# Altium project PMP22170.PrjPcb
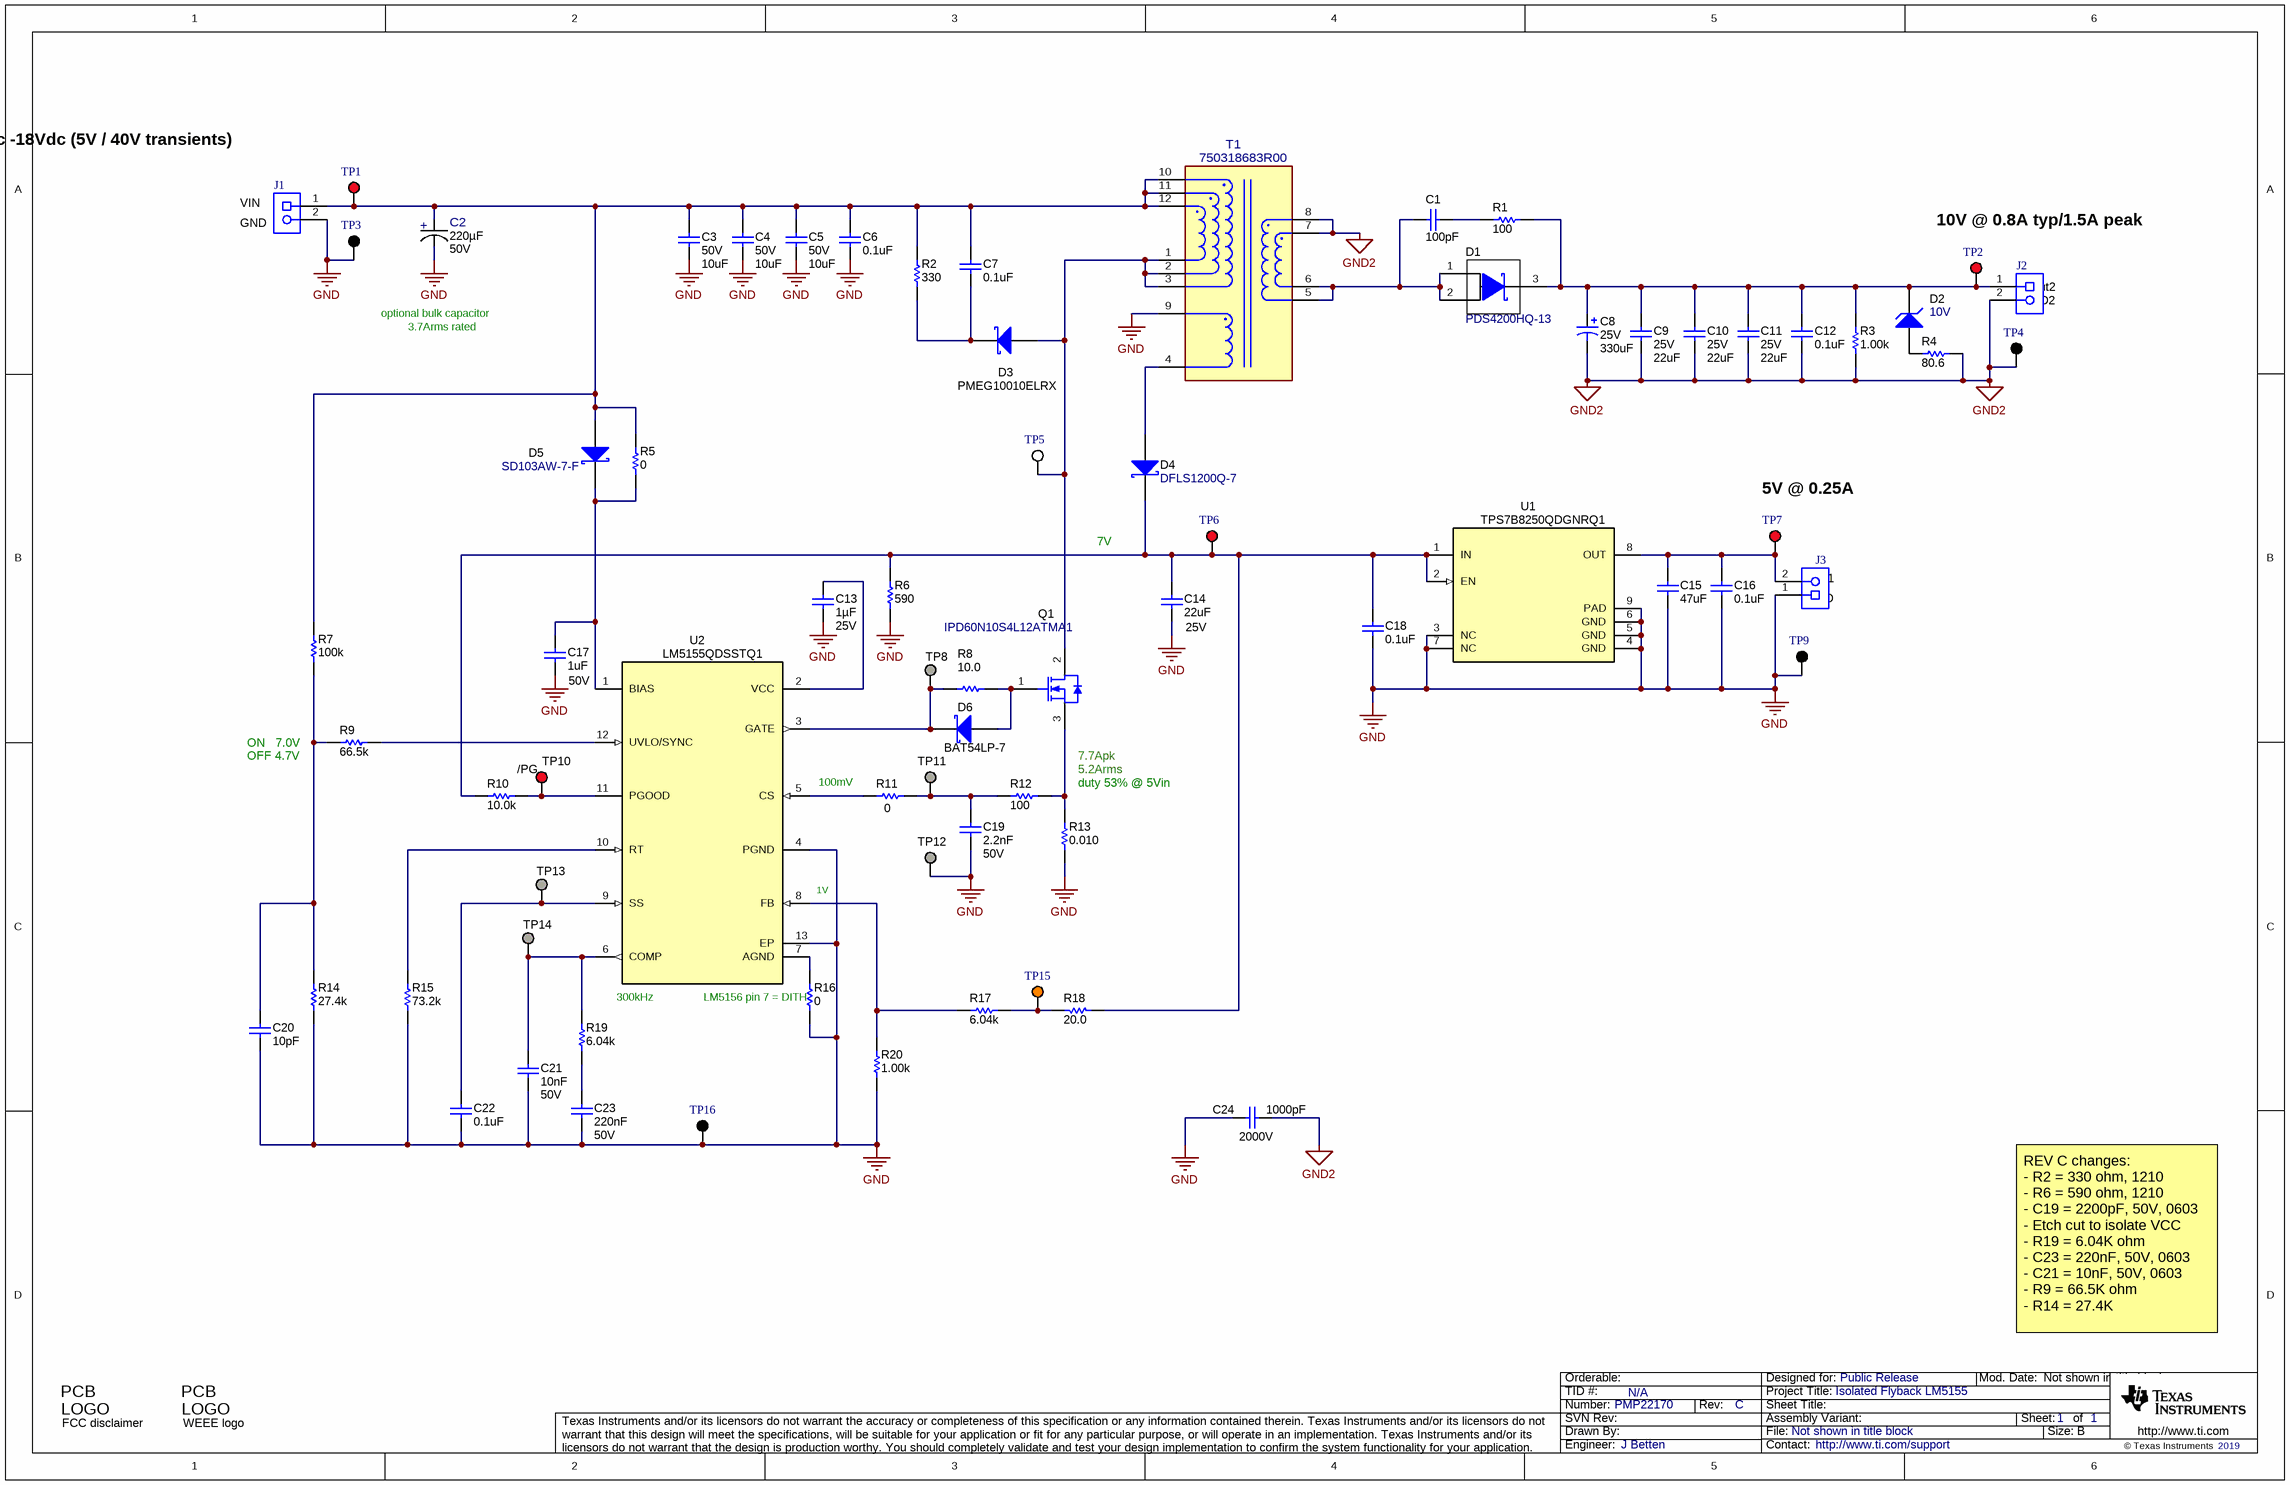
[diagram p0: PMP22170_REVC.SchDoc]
TID: N/A; TechSupport: http://www.ti.com/support; SCH_Rev: C; PRJ_Title: Isolated Flyback LM5155; PRJ_Number: PMP22170; PRJ_Engineer: J Betten; PRJ_Customer: Public Release; PCB_Rev: A; PCB_Layout: J Betten; CopyrightYear: 2019
1 sheet, 75 parts. Net scope: global (net labels, ports and power ports of the same name join across sheets).
Board file: PMP22170_REVA.PcbDoc

## Sheet PMP22170_REVC.SchDoc
size 431 x 279 mm; Date: Not shown in title block; ApprovedBy: Not shown in title block; CheckedBy: Not shown in title block; Author: Not shown in title block; CompanyName: Not shown in title block; Engineer: Not shown in title block; Organization: Not shown in title block; Address1: Not shown in title block; Address2: Not shown in title block; Address3: Not shown in title block; Address4: Not shown in title block; DocumentNumber: 1; Revision: Use project parameter SCH_Rev; SheetNumber: 1; SheetTotal: 1; PageSetup: Record=PageOptions¦CenterHorizontal=True¦CenterVertical=True¦PrintScale=1.00¦XCorrection=1.00¦YCorrection=1.00¦PrintKind=0¦BorderSize=5000000¦LeftOffset=0¦BottomOffset=0¦Orientation=2¦PaperLength=1000¦PaperWidth=1000¦Scale=100¦PaperSource=15¦PrintQuality=600¦MediaType=1¦DitherType=10¦PaperKind=Letter¦PrintScaleMode=1

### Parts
C1  ValueDisplayed: 100pF  [0805_HV]  (hidden comment: Capacitor)
C2  Cap_F: 220µF  VDC_V: 50V  [FP-EEHZS1H221P_RADIAL_SMD-MFG]  (hidden comment: EEH-ZS1H221V)
C3  VDC_V: 50V  ValueDisplayed: 10uF  [1210_280]  (hidden comment: UMK325AB7106KMHT)
C4  VDC_V: 50V  ValueDisplayed: 10uF  [1210_280]  (hidden comment: UMK325AB7106KMHT)
C5  VDC_V: 50V  ValueDisplayed: 10uF  [1210_280]  (hidden comment: UMK325AB7106KMHT)
C6  ValueDisplayed: 0.1uF  [0603]  (hidden comment: Capacitor)
C7  ValueDisplayed: 0.1uF  [0603]  (hidden comment: Capacitor)
C8  VDC_V: 25V  ValueDisplayed: 330uF  [SM_RADIAL_10BMM]  (hidden comment: EEHZC1E331P)
C9  VDC_V: 25V  ValueDisplayed: 22uF  [1210_270]  (hidden comment: TMK325B7226KMHT)
C10  VDC_V: 25V  ValueDisplayed: 22uF  [1210_270]  (hidden comment: TMK325B7226KMHT)
C11  VDC_V: 25V  ValueDisplayed: 22uF  [1210_270]  (hidden comment: TMK325B7226KMHT)
C12  ValueDisplayed: 0.1uF  [0603]  (hidden comment: Capacitor)
C13  Cap_F: 1µF  VDC_V: 25V  [0603]  (hidden comment: GCM188R71E105KA64D)
C14  ValueDisplayed: 22uF  Value2: 25V  [1210_270]  (hidden comment: Capacitor)
C15  ValueDisplayed: 47uF  [1210_270]  (hidden comment: Capacitor)
C16  ValueDisplayed: 0.1uF  [0603]  (hidden comment: Capacitor)
C17  ValueDisplayed: 1uF  Value2: 50V  [0805]  (hidden comment: Capacitor)
C18  ValueDisplayed: 0.1uF  [0603]  (hidden comment: Capacitor)
C19  Cap_F: 2.2nF  VDC_V: 50V  [0603]  (hidden comment: GRM188R71H222KA01D)
C20  ValueDisplayed: 10pF  [0603]  (hidden comment: Capacitor)
C21  Cap_F: 10nF  VDC_V: 50V  [0603]  (hidden comment: GCM188R71H103KA37D)
C22  ValueDisplayed: 0.1uF  [0603]  (hidden comment: Capacitor)
C23  Cap_F: 220nF  VDC_V: 50V  [0603]  (hidden comment: GCM188R71H224KA64D)
C24  ValueDisplayed: 1000pF  Value2: 2000V  [1808]  (hidden comment: Capacitor)
D1  PDS4200HQ-13  [POWERDI5]
D2  value 10V  [SOD-123]  (hidden comment: MMSZ5240B-7-F)
D3  PartNumber: PMEG10010ELRX  [SOD-123W]  (hidden comment: DIODE_SCHOTTKY)
D4  DFLS1200Q-7  [PowerDI123]
D5  SD103AW-7-F  [SOD-123]
D6  PartNumber: BAT54LP-7  [X1-DFN1006-2]  (hidden comment: DIODE_SCHOTTKY)
J1  Receptacle_2x1  [TERM_BLK_ED555-2DS]  (value not drawn)
J2  Receptacle_2x1  [TERM_BLK_ED555-2DS]  (value not drawn)
J3  Receptacle_2x1  [TERM_BLK_ED555-2DS]  (value not drawn)
Logo1  FCC disclaimer  [FCC_disclaimer]  (no BOM)
Logo2  WEEE logo  [WEEE_Minimum]  (no BOM)
Q1  IPD60N10S4L12ATMA1  [DPAK]
R1  ValueDisplayed: 100  [1206]  (hidden comment: CRCW1206100RFKEAHP)
R2  ValueDisplayed: 330  [1210]  (hidden comment: RC1210JR-07330RL)
R3  ValueDisplayed: 1.00k  [1210]  (hidden comment: ERJ14NF1001U)
R4  ValueDisplayed: 80.6  [0805_HV]  (hidden comment: CRCW080580R6FKEA)
R5  ValueDisplayed: 0  [0603]  (hidden comment: Resistor)
R6  ValueDisplayed: 590  [1210]  (hidden comment: RC1210FR-07590RL)
R7  ValueDisplayed: 100k  [0603]  (hidden comment: CRCW0603100KFKEA)
R8  ValueDisplayed: 10.0  [0603]  (hidden comment: Resistor)
R9  ValueDisplayed: 66.5k  [0603]  (hidden comment: CRCW060366K5FKEA)
R10  ValueDisplayed: 10.0k  [0603]  (hidden comment: CRCW060310K0FKEA)
R11  ValueDisplayed: 0  [0603]  (hidden comment: Resistor)
R12  ValueDisplayed: 100  [0603]  (hidden comment: Resistor)
R13  ValueDisplayed: 0.010  [1206]  (hidden comment: ERJ-8BWFR010V)
R14  ValueDisplayed: 27.4k  [0603]  (hidden comment: CRCW060327K4FKEA)
R15  ValueDisplayed: 73.2k  [0603]  (hidden comment: CRCW060373K2FKEA)
R16  ValueDisplayed: 0  [0402L]  (hidden comment: CRCW04020000Z0ED)
R17  ValueDisplayed: 6.04k  [0603]  (hidden comment: Resistor)
R18  ValueDisplayed: 20.0  [0603]  (hidden comment: CRCW060320R0FKEA)
R19  ValueDisplayed: 6.04k  [0603]  (hidden comment: CRCW06036K04FKEA)
R20  ValueDisplayed: 1.00k  [0603]  (hidden comment: CRCW06031K00FKEA)
T1  750318683R00  [FP-750318683R00_SMT_TRANSFORMER-MFG]
TP1  5000  [Keystone5000]  (value not drawn)
TP2  5000  [Keystone5000]  (value not drawn)
TP3  5001  [Keystone5001]  (value not drawn)
TP4  5001  [Keystone5001]  (value not drawn)
TP5  5002  [Keystone5002]  (value not drawn)
TP6  5000  [Keystone5000]  (value not drawn)
TP7  5000  [Keystone5000]  (value not drawn)
TP8  TP_SM_1MM  [TP_SM_1MM]  (value not drawn)  (no BOM)
TP9  5001  [Keystone5001]  (value not drawn)
TP10  5000  [Keystone5000]  (value not drawn)
TP11  TP_SM_1MM  [TP_SM_1MM]  (value not drawn)  (no BOM)
TP12  TP_SM_1MM  [TP_SM_1MM]  (value not drawn)  (no BOM)
TP13  TP_SM_1MM  [TP_SM_1MM]  (value not drawn)  (no BOM)
TP14  TP_SM_1MM  [TP_SM_1MM]  (value not drawn)  (no BOM)
TP15  5003  [Keystone5003]  (value not drawn)
TP16  5001  [Keystone5001]  (value not drawn)
U1  TPS7B8250QDGNRQ1  [DGN0008D_N]
U2  LM5155QDSSTQ1  [DSS0012C]

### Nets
GND: C2.1(CATHODE) C3.2 C4.2 C5.2 C6.2 C13.2 C14.2 C15.2 C16.2 C17.2 C18.2 C19.2 C20.2 C21.2 C22.2 C23.2 C24.2 J1.2 J3.1 R6.1 R13.1 R14.1 R15.1 R16.1 R20.1 T1.9 TP3.1 TP9.1 TP12.1 TP16.1 U1.3(NC) U1.4(GND) U1.5(GND) U1.6(GND) U1.7(NC) U1.9(PAD) U2.4(PGND) U2.13(EP)
GND2: C8.2(-) C9.2 C10.2 C11.2 C12.2 C24.1 J2.2 R3.1 R4.1 T1.7 T1.8 TP4.1
PG: R10.2 TP10.1 U2.11(PGOOD)
NetC1_1: C1.1 R1.1
NetC1_2: C1.2 D1.1(A) D1.2(A) T1.5 T1.6
NetC2_2: C2.2(ANODE) C3.1 C4.1 C5.1 C6.1 C7.1 D5.2(A) J1.1 R2.2 R5.2 R7.2 T1.10 T1.11 T1.12 TP1.1
NetC7_2: C7.2 D3.1(K) R2.1
NetC8_1: C8.1(+) C9.1 C10.1 C11.1 C12.1 D1.3(K) D2.1(K) J2.1 R1.2 R3.2 TP2.1
NetC13_1: C13.1 U2.2(VCC)
NetC14_1: C14.1 C18.1 D4.1(K) R6.2 R10.1 R18.2 TP6.1 U1.1(IN) U1.2(EN)
NetC15_1: C15.1 C16.1 J3.2 TP7.1 U1.8(OUT)
NetC17_1: C17.1 D5.1(K) R5.1 U2.1(BIAS)
NetC19_1: C19.1 R11.2 R12.1 TP11.1
NetC20_1: C20.1 R7.1 R9.1 R14.2
NetC21_1: C21.1 R19.2 TP14.1 U2.6(COMP)
NetC22_1: C22.1 TP13.1 U2.9(SS)
NetC23_1: C23.1 R19.1
NetD2_2: D2.2(A) R4.2
NetD3_2: D3.2(A) Q1.2(D) T1.1 T1.2 T1.3 TP5.1
NetD4_2: D4.2(A) T1.4
NetD6_1: D6.1(K) R8.2 TP8.1 U2.3(GATE)
NetD6_2: D6.2(A) Q1.1(G) R8.1
NetQ1_3: Q1.3(S) R12.2 R13.2
NetR9_2: R9.2 U2.12(UVLO/SYNC)
NetR11_1: R11.1 U2.5(CS)
NetR15_2: R15.2 U2.10(RT)
NetR16_2: R16.2 U2.7(AGND)
NetR17_1: R17.1 R18.1 TP15.1
NetR17_2: R17.2 R20.2 U2.8(FB)

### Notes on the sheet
- Input 6Vdc -18Vdc (5V / 40V transients)
- (near J1) VIN
- (near J1) GND
- 10V @ 0.8A typ/1.5A peak
- (near J2) Vout2
- GND2
- optional bulk capacitor
- 3.7Arms rated
- (near TP7) 5V @ 0.25A
- 7V
- (near J3) Vout1
- (near J3) GND
- (near R9) ON   7.0V
- (near R9) OFF 4.7V
- (near TP10) /PG
- 7.7Apk
- 5.2Arms
- 100mV
- duty 53% @ 5Vin
- (near U2) 1V
- 300kHz
- (near R16) LM5156 pin 7 = DITH
- REV C changes:
  - R2 = 330 ohm, 1210
  - R6 = 590 ohm, 1210
  - C19 = 2200pF, 50V, 0603
  - Etch cut to isolate VCC
  - R19 = 6.04K ohm
  - C23 = 220nF, 50V, 0603
  - C21 = 10nF, 50V, 0603
  - R9 = 66.5K ohm
  - R14 = 27.4K

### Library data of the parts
C1 = CMP-0008236-2: CAP, CERM, 100 pF, 250 V, +/- 5%, C0G/NP0, 0805; PartNumber: GRM21A5C2E101JW01D; Manufacturer: MuRata; Polarized: N; Value: 100pF; U/M: EA; Value1: Unknown; VDC_V: 250V; TaMin_C: -55°C; TaMax_C: 125°C; Cap_Case: 0805; SizeArea_mm2: 2.5; SizeAreaWB_mm2: 6.75; SizeX_mm: 2; SizeY_mm: 1.25; SizeZ_mm: 1.45; AEC Category: Q200
C2 = CMP-0087071-1: 220µF 50V Aluminum Polymer Capacitor Radial, Can - SMD 13 mOhm 4000 Hrs @ 125°C; Manufacturer: Panasonic; SizeZ_mm: 16.8mm; AEC Grade: Grade 1; Symbol Name: SYM-EEHZS1H221P; IRMS_A: 3.7A; Tolerance_%: 20%; AEC Qualified: Yes
C3-C5 = CMP-0009258-2: CAP, CERM, 10 uF, 50 V, +/- 10%, X7R, AEC-Q200 Grade 1, 1210; Manufacturer: Taiyo Yuden; TaMin_C: -55°C; Polarized: N; SizeAreaWB_mm2: 14.7; Value1: Unknown; U/M: EA; Value: 10uF; TaMax_C: 125°C; SizeZ_mm: 2.8; SizeX_mm: 3.2; SizeY_mm: 2.5; Cap_Case: 1210; SizeArea_mm2: 8; AEC Qualified: Y; Cap_F: 10µF; AEC Grade: 1; AEC Category: Q200
C6 C7 C12 = CMP-0007144-4: CAP, CERM, 0.1 uF, 50 V, +/- 10%, X7R, 0603; PartNumber: GCM188R71H104KA57D; Manufacturer: MuRata; Polarized: N; Value: 0.1uF; U/M: EA; Cap_F: 100nF; ESR_ohm: 0.02; Value1: 0.02 ohm; VDC_V: 50V; IRMS_A: 1.84A; TaMin_C: -55°C; TaMax_C: 125°C; AEC Category: Q200; SizeArea_mm2: 1.28; SizeAreaWB_mm2: 4.68; SizeX_mm: 1.6; SizeY_mm: 0.8; SizeZ_mm: 1
C8 = CMP-0012593-3: CAP, Polymer Hybrid, 330 uF, 25 V, +/- 20%, 20 mohm, 10x10 SMD; Manufacturer: Panasonic; TaMin_C: -55°C; ESR_ohm: 20; Polarized: Y; SizeAreaWB_mm2: 159.9; Value1: 20 ohm; Value: 330uF; TaMax_C: 125°C; SizeZ_mm: 10.2; SizeX_mm: 11; SizeY_mm: 10.3; SizeArea_mm2: 113.3; CompType: Capacitor; Cap_F: 330µF; IRMS_A: 2A; AEC Category: Q200
C9-C11 = CMP-0009255-2: CAP, CERM, 22 uF, 25 V, +/- 10%, X7R, AEC-Q200 Grade 1, 1210; Manufacturer: Taiyo Yuden; TaMin_C: -55°C; Polarized: N; SizeAreaWB_mm2: 14.7; Value1: Unknown; U/M: EA; Value: 22uF; TaMax_C: 125°C; SizeZ_mm: 2.7; SizeX_mm: 3.2; SizeY_mm: 2.5; Cap_Case: 1210; SizeArea_mm2: 8; AEC Qualified: Y; Cap_F: 22µF; AEC Grade: 1; AEC Category: Q200
C13 = CMP-0007139-4: CAP, CERM, 1 uF, 25 V, +/- 10%, X7R, AEC-Q200 Grade 1, 0603; Manufacturer: MuRata; TaMin_C: -55°C; Polarized: N; SizeAreaWB_mm2: 4.68; Value1: Unknown; U/M: EA; Value: 1uF; TaMax_C: 125°C; SizeZ_mm: 1; SizeX_mm: 1.6; SizeY_mm: 0.8; SizeArea_mm2: 1.28; AEC Qualified: Y; AEC Category: Q200
C14 = CMP-0009224-2: CAP, CERM, 22 uF, 25 V, +/- 10%, X7R, 1210; PartNumber: GRM32ER71E226KE15L; Manufacturer: MuRata; Polarized: N; Value: 22uF; U/M: EA; Cap_F: 22µF; Value1: Unknown; TaMin_C: -55°C; TaMax_C: 125°C; Cap_Case: 1210; SizeArea_mm2: 8; SizeAreaWB_mm2: 14.7; SizeX_mm: 3.2; SizeY_mm: 2.5; SizeZ_mm: 2.7; AEC Category: Q200
C15 = CMP-0009220-2: CAP, CERM, 47 uF, 10 V, +/- 10%, X7R, 1210; PartNumber: GRM32ER71A476KE15L; Manufacturer: MuRata; Polarized: N; Value: 47uF; U/M: EA; Cap_F: 47µF; Value1: Unknown; VDC_V: 10V; TaMin_C: -55°C; TaMax_C: 125°C; Cap_Case: 1210; SizeArea_mm2: 8; SizeAreaWB_mm2: 14.7; SizeX_mm: 3.2; SizeY_mm: 2.5; SizeZ_mm: 2.7; AEC Category: Q200
C16 C18 C22 = CMP-0007378-5: CAP, CERM, 0.1 uF, 16 V, +/- 10%, X7R, 0603; PartNumber: GRM188R71C104KA01D; Manufacturer: MuRata; Polarized: N; Value: 0.1uF; U/M: EA; Cap_F: 100nF; Value1: Unknown; VDC_V: 16V; TaMin_C: -55°C; TaMax_C: 125°C; SizeArea_mm2: 1.28; SizeAreaWB_mm2: 4.68; SizeX_mm: 1.6; SizeY_mm: 0.8; SizeZ_mm: 1; AEC Category: Q200
C17 = CMP-0008350-2: CAP, CERM, 1 uF, 50 V, +/- 10%, X7R, 0805; PartNumber: GRM21BR71H105KA12L; Manufacturer: MuRata; Polarized: N; Value: 1uF; U/M: EA; Cap_F: 1µF; Value1: Unknown; TaMin_C: -55°C; TaMax_C: 125°C; SizeArea_mm2: 2.5; SizeAreaWB_mm2: 6.75; SizeX_mm: 2; SizeY_mm: 1.25; SizeZ_mm: 1.45; AEC Category: Q200
C19 = CMP-0007443-4: CAP, CERM, 2200 pF, 50 V, +/- 10%, X7R, 0603; Manufacturer: MuRata; TaMin_C: -55°C; Polarized: N; SizeAreaWB_mm2: 4.68; Value1: Unknown; U/M: EA; Value: 2200pF; TaMax_C: 125°C; SizeZ_mm: 1; SizeX_mm: 1.6; SizeY_mm: 0.8; SizeArea_mm2: 1.28; AEC Category: Q200
C20 = CMP-0007170-4: CAP, CERM, 10 pF, 50 V, +/- 5%, C0G/NP0, 0603; PartNumber: GRM1885C1H100JA01D; Manufacturer: MuRata; Polarized: N; Value: 10pF; U/M: EA; Value1: Unknown; VDC_V: 50V; TaMin_C: -55°C; TaMax_C: 125°C; SizeArea_mm2: 1.28; SizeAreaWB_mm2: 4.68; SizeX_mm: 1.6; SizeY_mm: 0.8; SizeZ_mm: 1; AEC Category: Q200
C21 = CMP-0007143-4: CAP, CERM, 0.01 uF, 50 V, +/- 10%, X7R, AEC-Q200 Grade 1, 0603; Manufacturer: MuRata; TaMin_C: -55°C; Polarized: N; SizeAreaWB_mm2: 4.68; Value1: Unknown; U/M: EA; Value: 0.01uF; TaMax_C: 125°C; SizeZ_mm: 1; SizeX_mm: 1.6; SizeY_mm: 0.8; SizeArea_mm2: 1.28; AEC Qualified: Y; AEC Category: Q200
C23 = CMP-0007145-4: CAP, CERM, 0.22 uF, 50 V, +/- 10%, X7R, AEC-Q200 Grade 1, 0603; Manufacturer: MuRata; TaMin_C: -55°C; Polarized: N; SizeAreaWB_mm2: 4.68; Value1: Unknown; U/M: EA; Value: 0.22uF; TaMax_C: 125°C; SizeZ_mm: 1; SizeX_mm: 1.6; SizeY_mm: 0.8; SizeArea_mm2: 1.28; AEC Qualified: Y; AEC Category: Q200
C24 = CMP-0009436-2: CAP, CERM, 1000 pF, 2000 V, +/- 10%, X7R, 1808; PartNumber: GR442QR73D102KW01L; Manufacturer: MuRata; Polarized: N; Value: 1000pF; U/M: EA; Cap_F: 1nF; Value1: Unknown; VDC_V: 2kV; TaMin_C: -55°C; TaMax_C: 125°C; SizeArea_mm2: 9; SizeAreaWB_mm2: 16.5; SizeX_mm: 4.5; SizeY_mm: 2; SizeZ_mm: 2.03; AEC Category: Q200
D1 = CMP-0081019-2: Diode, Schottky, 200 V, 4 A, AEC-Q101, PowerDI5; Manufacturer: Diodes Inc.; Vf_V: 840mV; Io_A: 4A; SizeX_mm: 6.4; Vr_V: 200V; Value2: 0.84V; AEC Category: Q101; TJmax_C: 175°C; SizeAreaWB_mm2: 49.56; SizeArea_mm2: 24.96; Value: 200V; AEC Qualified: Y; SizeY_mm: 3.9; SizeZ_mm: 1.05
D2 = CMP-0005749-3: Diode, Zener, 10 V, 500 mW, SOD-123; Manufacturer: Diodes Inc.; AEC Category: Q101; SizeX_mm: 3.85; SizeAreaWB_mm2: 13.095; SizeY_mm: 1.7; RJA_CperW: 350; Power_W: 500mW; Value1: 0.5W; SizeZ_mm: 1.35; SizeArea_mm2: 6.545
D3 = CMP-0028782-2: Diode, Schottky, 100 V, 1 A, AEC-Q101, SOD-123W; Manufacturer: Nexperia; Vf_V: 770mV; Value: 100V; Value1: 1A; Value2: 0.77V; TJmax_C: 175°C; SizeAreaWB_mm2: 12.15; SizeArea_mm2: 5.95; SizeX_mm: 3.5; SizeY_mm: 1.7; SizeZ_mm: 1; AEC Category: Q101; AEC Qualified: Y; Green_Lifecycle: Not Set; Green_REACh: Incomplete
D4 = CMP-0028517-2: Diode, Schottky, 200 V, 1 A, PowerDI123; Manufacturer: Diodes Inc.; Vr_V: 200V; SizeZ_mm: 0.98; Value: 200V; TJmax_C: 175°C; SizeY_mm: 1.78; Vf_V: 850mV; Green_REACh: Passed; Io_A: 1A; Value2: 0.85V; SizeAreaWB_mm2: 13.066; SizeArea_mm2: 6.586; Green_Lifecycle: Active; AEC Category: Q101; SizeX_mm: 3.7; RJC_CperW: 7
D5 = CMP-0028543-1: Diode, Schottky, 40 V, 0.35 A, SOD-123; Manufacturer: Diodes Inc.; Io_A: 350mA; Green_Lifecycle: Active; SizeAreaWB_mm2: 13.095; Vr_V: 40V; Green_REACh: Passed; Value1: 0.35A; U/M: EA; Value: 40V; SizeZ_mm: 1.35; SizeX_mm: 3.85; SizeY_mm: 1.7; Vf_V: 550mV; Value2: 0.55V; SizeArea_mm2: 6.545; AEC Category: Q101
D6 = CMP-0076931-2: Diode, Schottky, 30 V, 0.2 A, 1.00x0.50x0.60mm; Manufacturer: Diodes Inc.; Vf_V: 1V; Value: 30V; Value1: 0.2A; Io_A: 200mA; SizeAreaWB_mm2: 3.2; SizeArea_mm2: 0.6; SizeX_mm: 1.0; SizeZ_mm: 0.53; AEC Category: Q101; Green_Lifecycle: Not Set; Green_REACh: Incomplete
J1-J3 = CMP-0074913-1: Terminal Block, 3.5mm Pitch, 2x1, TH; PartNumber: ED555/2DS; Manufacturer: On-Shore Technology; Cert_CULUS: Y; CNHeader: False; ContactFinish: Brass; CT: True; Current_A: 6A; Gender: Female; Green_Lifecycle: Active; Green_REACh: Passed; Pitch_mm: 3.5; Row_Count: 1; Shrouded: N; Voltage_V: 150V
Logo1 = CMP-0074847-1: FCC_disclaimer; Library Reference: Logo
Logo2 = CMP-0074769-1
Q1 = CMP-0080670-2: MOSFET, N-CH, 100 V, 60 A, AEC-Q101, DPAK; Manufacturer: Infineon Technologies; Alternate Manufacturer: None; QgTyp_nC: 38; AEC Category: Q101; Vgs_V: 16V; Value1: 0.015 ohm; SizeAreaWB_mm2: 101.7114; IdsMax_A: 60A; SizeX_mm: 9.91; SizeArea_mm2: 64.8114; Value: 100V; Value2: 38 nC; Rdson45_ohm: 0.015; SizeY_mm: 6.54; ChType: N; AEC Qualified: Y; ChMode: Enhancement; SizeZ_mm: 2.29
R1 = CMP-0016570-3: RES, 100, 1%, 0.5 W, AEC-Q200 Grade 0, 1206; Manufacturer: Vishay-Dale; Power_W: 500mW; TempCo: 100 ppm/C; Value_Code: 100R; Value: 100; EIA_Code: E96; SizeX_mm: 3.2; SizeY_mm: 1.6; SizeZ_mm: 1.35; Value2: 0.5W; SizeArea_mm2: 5.12; AEC Qualified: Y; AEC Grade: 0; AEC Category: Q200
R2 = CMP-0083529-1: RES, 330, 5%, 0.5 W, 1210; Manufacturer: Yageo; Power_W: 500mW; TempCo: 100 ppm/C; SizeAreaWB_mm2: 14.7; Value_Code: 330R; Value: 330; EIA_Code: E24; SizeX_mm: 3.2; SizeY_mm: 2.5; SizeZ_mm: 1.35; Value2: 0.5W; SizeArea_mm2: 8; AEC Qualified: N; VDC_V: 200V; AEC Category: Q200
R3 = CMP-0015030-3: RES, 1.00 k, 1%, 0.5 W, AEC-Q200 Grade 0, 1210; Manufacturer: Panasonic; Power_W: 500mW; TempCo: 100 ppm/C; SizeAreaWB_mm2: 14.7; Value_Code: 1k00; Value: 1.00k; EIA_Code: E96; Res_ohm: 1k; SizeX_mm: 3.2; SizeY_mm: 2.5; SizeZ_mm: 1.35; Value2: 0.5W; SizeArea_mm2: 8; AEC Qualified: Y; VDC_V: 22V; AEC Category: Q200; AEC Grade: 0
R4 = CMP-0021452-3: RES, 80.6, 1%, 0.125 W, AEC-Q200 Grade 0, 0805; Manufacturer: Vishay-Dale; Power_W: 125mW; TempCo: 100 ppm/C; Value_Code: 80R6; Value: 80.6; EIA_Code: E96; SizeX_mm: 2; SizeY_mm: 1.25; SizeZ_mm: 1.45; Value2: 0.125W; SizeArea_mm2: 2.5; AEC Qualified: Y; VDC_V: 150V; AEC Category: Q200; AEC Grade: 0
R5 R11 = CMP-0025697-4: RES, 0, 5%, 0.1 W, AEC-Q200 Grade 0, 0603; PartNumber: CRCW06030000Z0EA; Manufacturer: Vishay-Dale; Value: 0; Value_Code: 0000; Power_W: 100mW; Value2: 0.1W; VDC_V: 75V; TempCo: 200 ppm/C; SizeArea_mm2: 1.28; SizeX_mm: 1.6; SizeY_mm: 0.8; SizeZ_mm: 1; EIA_Code: E24; AEC Category: Q200; AEC Qualified: Y
R6 = CMP-0083268-1: RES, 590, 1%, 0.5 W, 1210; Manufacturer: Yageo; Power_W: 500mW; TempCo: 100 ppm/C; SizeAreaWB_mm2: 14.7; Value_Code: 590R; Value: 590; EIA_Code: E96; SizeX_mm: 3.2; SizeY_mm: 2.5; SizeZ_mm: 1.35; Value2: 0.5W; SizeArea_mm2: 8; AEC Qualified: N; VDC_V: 200V; AEC Category: Q200
R7 = CMP-0021990-4: RES, 100 k, 1%, 0.1 W, AEC-Q200 Grade 0, 0603; Manufacturer: Vishay-Dale; Power_W: 100mW; TempCo: 100 ppm/C; Value: 100k; EIA_Code: E96; SizeX_mm: 1.6; SizeY_mm: 0.8; SizeZ_mm: 1; Value2: 0.1W; SizeArea_mm2: 1.28; AEC Qualified: Y; VDC_V: 75V; AEC Category: Q200; AEC Grade: 0
R8 = CMP-0022003-4: RES, 10.0, 1%, 0.1 W, AEC-Q200 Grade 0, 0603; PartNumber: CRCW060310R0FKEA; Manufacturer: Vishay-Dale; Value: 10.0; Res_ohm: 10; Value_Code: 10R0; Power_W: 100mW; Value2: 0.1W; VDC_V: 75V; TempCo: 100 ppm/C; SizeArea_mm2: 1.28; SizeX_mm: 1.6; SizeY_mm: 0.8; SizeZ_mm: 1; EIA_Code: E96; AEC Category: Q200; AEC Qualified: Y; AEC Grade: 0
R9 = CMP-0022548-4: RES, 66.5 k, 1%, 0.1 W, AEC-Q200 Grade 0, 0603; Manufacturer: Vishay-Dale; Power_W: 100mW; TempCo: 100 ppm/C; Value_Code: 66k5; Value: 66.5k; EIA_Code: E96; SizeX_mm: 1.6; SizeY_mm: 0.8; SizeZ_mm: 1; Value2: 0.1W; SizeArea_mm2: 1.28; AEC Qualified: Y; VDC_V: 75V; AEC Category: Q200; AEC Grade: 0
R10 = CMP-0021998-4: RES, 10.0 k, 1%, 0.1 W, AEC-Q200 Grade 0, 0603; Manufacturer: Vishay-Dale; Power_W: 100mW; TempCo: 100 ppm/C; Value_Code: 10k0; Value: 10.0k; EIA_Code: E96; Res_ohm: 10k; SizeX_mm: 1.6; SizeY_mm: 0.8; SizeZ_mm: 1; Value2: 0.1W; SizeArea_mm2: 1.28; AEC Qualified: Y; VDC_V: 75V; AEC Category: Q200; AEC Grade: 0
R12 = CMP-0021991-4: RES, 100, 1%, 0.1 W, AEC-Q200 Grade 0, 0603; PartNumber: CRCW0603100RFKEA; Manufacturer: Vishay-Dale; Value: 100; Value_Code: 100R; Power_W: 100mW; Value2: 0.1W; VDC_V: 75V; TempCo: 100 ppm/C; SizeArea_mm2: 1.28; SizeX_mm: 1.6; SizeY_mm: 0.8; SizeZ_mm: 1; EIA_Code: E96; AEC Category: Q200; AEC Qualified: Y; AEC Grade: 0
R13 = CMP-0750151-1: RES, 0.010, 1%, 1 W, AEC-Q200 Grade 0, 1206; Manufacturer: Panasonic; SizeZ_mm: 1.35; Value_Code: R010; Value2: 1W; AEC Category: Q200; Value: 0.010; SizeAreaWB_mm2: 10.92; TempCo: 200 ppm/C; SizeY_mm: 1.6; SizeArea_mm2: 5.12; SizeX_mm: 3.2; AEC Grade: 0; EIA_Code: E96; AEC Qualified: Y
R14 = CMP-0022254-4: RES, 27.4 k, 1%, 0.1 W, AEC-Q200 Grade 0, 0603; Manufacturer: Vishay-Dale; Power_W: 100mW; TempCo: 100 ppm/C; Value_Code: 27k4; Value: 27.4k; EIA_Code: E96; SizeX_mm: 1.6; SizeY_mm: 0.8; SizeZ_mm: 1; Value2: 0.1W; SizeArea_mm2: 1.28; AEC Qualified: Y; VDC_V: 75V; AEC Category: Q200; AEC Grade: 0
R15 = CMP-0022585-4: RES, 73.2 k, 1%, 0.1 W, AEC-Q200 Grade 0, 0603; Manufacturer: Vishay-Dale; Power_W: 100mW; TempCo: 100 ppm/C; Value_Code: 73k2; Value: 73.2k; EIA_Code: E96; SizeX_mm: 1.6; SizeY_mm: 0.8; SizeZ_mm: 1; Value2: 0.1W; SizeArea_mm2: 1.28; AEC Qualified: Y; VDC_V: 75V; AEC Category: Q200; AEC Grade: 0
R16 = CMP-0026822-3: RES, 0, 5%, 0.063 W, AEC-Q200 Grade 0, 0402; Manufacturer: Vishay-Dale; Power_W: 63mW; TempCo: 200 ppm/C; Value_Code: 0000; Value: 0; EIA_Code: E24; SizeX_mm: 1; SizeY_mm: 0.5; SizeZ_mm: 0.6; Value2: 0.063W; AEC Qualified: Y; VDC_V: 50V; AEC Category: Q200
R17 = CMP-0022558-4: RES, 6.04 k, 1%, 0.1 W, AEC-Q200 Grade 0, 0603; PartNumber: CRCW06036K04FKEA; Manufacturer: Vishay-Dale; Value: 6.04k; Value_Code: 6k04; Power_W: 100mW; Value2: 0.1W; VDC_V: 75V; TempCo: 100 ppm/C; SizeArea_mm2: 1.28; SizeX_mm: 1.6; SizeY_mm: 0.8; SizeZ_mm: 1; EIA_Code: E96; AEC Category: Q200; AEC Qualified: Y; AEC Grade: 0
R18 = CMP-0022206-4: RES, 20.0, 1%, 0.1 W, AEC-Q200 Grade 0, 0603; Manufacturer: Vishay-Dale; Power_W: 100mW; TempCo: 100 ppm/C; Value_Code: 20R0; Value: 20.0; EIA_Code: E96; Res_ohm: 20; SizeX_mm: 1.6; SizeY_mm: 0.8; SizeZ_mm: 1; Value2: 0.1W; SizeArea_mm2: 1.28; AEC Qualified: Y; VDC_V: 75V; AEC Category: Q200; AEC Grade: 0
R19 = CMP-0022558-4: RES, 6.04 k, 1%, 0.1 W, AEC-Q200 Grade 0, 0603; Manufacturer: Vishay-Dale; Power_W: 100mW; TempCo: 100 ppm/C; Value_Code: 6k04; Value: 6.04k; EIA_Code: E96; SizeX_mm: 1.6; SizeY_mm: 0.8; SizeZ_mm: 1; Value2: 0.1W; SizeArea_mm2: 1.28; AEC Qualified: Y; VDC_V: 75V; AEC Category: Q200; AEC Grade: 0
R20 = CMP-0022109-5: RES, 1.00 k, 1%, 0.1 W, AEC-Q200 Grade 0, 0603; Manufacturer: Vishay-Dale; Power_W: 100mW; TempCo: 100 ppm/C; Value_Code: 1k00; Value: 1.00k; EIA_Code: E96; Res_ohm: 1k; SizeX_mm: 1.6; SizeY_mm: 0.8; SizeZ_mm: 1; Value2: 0.1W; SizeArea_mm2: 1.28; AEC Qualified: Y; VDC_V: 75V; AEC Category: Q200; AEC Grade: 0
T1 = CMP-0086930-1: TRANSFORMER, 7uH, SMT; Manufacturer: Wurth Electronics; Ind_H: 7µH; Rsec1_ohm: 0.058; SizeZ_mm: 13.69mm; AEC Qualified: No; DCR_ohm: 0.01; Ns1toNp: 1.44:1, 2:1
TP1 TP2 TP6 TP7 TP10 = CMP-0055137-1: Test Point, Miniature, Red, TH; Manufacturer: Keystone; CNHeader: FALSE; ContactFinish: Silver; CT: TRUE; Green_Lifecycle: Active; Green_REACh: Passed
TP3 TP4 TP9 TP16 = CMP-0055138-1: Test Point, Miniature, Black, TH; Manufacturer: Keystone; CNHeader: FALSE; ContactFinish: Silver; CT: TRUE; Green_Lifecycle: Active; Green_REACh: Passed
TP5 = CMP-0055139-1: Test Point, Miniature, White, TH; Manufacturer: Keystone; ContactFinish: Silver; CNHeader: FALSE; CT: TRUE; Green_Lifecycle: Active; Green_REACh: Passed
TP8 TP11-TP14 = CMP-0003825-1: 1mm Test Point, SMT; Manufacturer: Any
TP15 = CMP-0055140-1: Test Point, Miniature, Orange, TH; Manufacturer: Keystone; ContactFinish: Silver; CNHeader: FALSE; CT: TRUE; Green_Lifecycle: Active; Green_REACh: Passed
U1 = CMP-0013313-4: 300mA High-Voltage Ultra-Low-Iq Low-Dropout (LDO) Regulator, DGN0008D (VSSOP-8); Manufacturer: Texas Instruments; SizeX_mm: 5.05; SizeY_mm: 3.1; CompType: IC; SizeZ_mm: 1.1; SizeArea_mm2: 15.655; SizeAreaWB_mm2: 35.955; AEC Category: Q200; AEC Qualified: Y
U2 = CMP-0081538-1: Automotive Grade 2.2-MHz Wide Input Non-synchronous Boost Controller, DSS0012C (WSON-12); Alternate PartNumber: LM5155QDSSRQ1; Alternate Manufacturer: Texas Instruments; SizeAreaWB_mm2: 12; SizeZ_mm: 0.8; SizeX_mm: 2; SizeY_mm: 3; SizeArea_mm2: 6; CompType: IC; AEC Qualified: Y; AEC Category: Q200

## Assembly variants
001: not fitted C10 C11 R3 R5 R6 R10 TP10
